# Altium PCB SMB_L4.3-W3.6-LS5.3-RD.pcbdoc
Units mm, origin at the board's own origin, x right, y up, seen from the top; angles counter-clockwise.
Board outline 19.5 x 16.61 mm, 2 copper layers (Top Layer, Bottom Layer), stack 0.07 mm thick; 1 components, 0 nets, 2 pads, 0 vias.
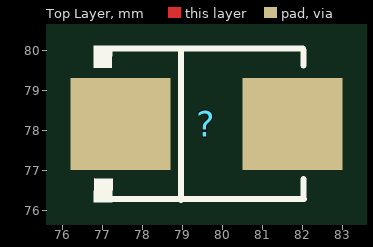
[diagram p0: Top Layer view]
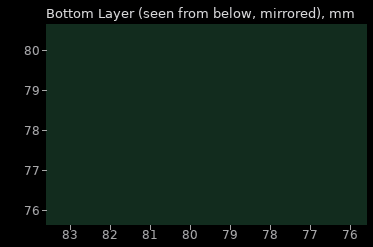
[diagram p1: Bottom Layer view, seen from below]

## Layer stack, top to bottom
Top Solder Mask Layer: solder mask 0.01, Dk 3.3
Top Layer: signal copper 0.035
Bottom Layer: signal copper 0.035
Bottom Solder Mask Layer: solder mask 0.01, Dk 3.3

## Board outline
89.35,69.85 69.85,69.85 69.85,86.461 89.35,86.461

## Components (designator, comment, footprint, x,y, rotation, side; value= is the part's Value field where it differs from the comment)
? "SMB_L4.3-W3.6-LS5.3-RD" SMB_L4.3-W3.6-LS5.3-RD 79.6,78.162 r0 top

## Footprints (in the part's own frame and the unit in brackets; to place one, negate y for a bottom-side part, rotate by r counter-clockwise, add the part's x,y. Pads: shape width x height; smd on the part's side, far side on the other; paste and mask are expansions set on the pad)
SMB_L4.3-W3.6-LS5.3-RD [mm]
  rect 2.5x2.3 smd paste+0 mask+0.051: 1(-2.15,0) 2(2.15,0)
  silkscreen extent -2.81,-1.96 2.43,1.95

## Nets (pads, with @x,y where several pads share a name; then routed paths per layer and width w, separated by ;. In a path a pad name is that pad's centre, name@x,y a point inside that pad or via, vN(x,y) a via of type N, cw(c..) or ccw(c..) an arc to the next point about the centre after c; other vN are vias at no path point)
pads on no net: ?.1 ?.2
